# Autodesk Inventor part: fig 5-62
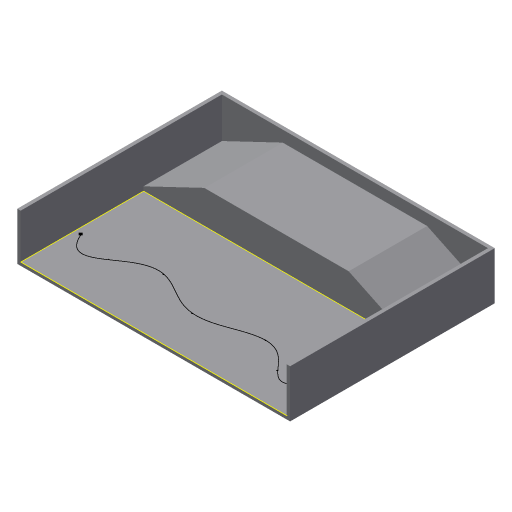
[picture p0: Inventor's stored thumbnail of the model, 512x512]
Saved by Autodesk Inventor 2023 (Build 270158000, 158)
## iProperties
Created: 2004-05
Part Number: fig 5-62
Document SubType Name: Modeling
Designer: CADCIM Technologies
Manufacturer: Standard
Standards Organization: Custom
Density: 1 g/cm^3
Material: Generic
Appearance: Default
Author: CADCIM Technologies
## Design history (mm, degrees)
sketch "Sketch1"
  geometry: L1 (-40, -30)-(40, -30); L2 (40, -30)-(40, 30); L3 (40, 30)-(-40, 30); L4 (-40, 30)-(-40, -30); 1 further point
  constraints: 8 end point, 2 parallel, 1 horizontal, 1 perpendicular, 1 other
  dimensions: "d0" = 80 distance of L1.start L1.end; "d1" = 60 distance of L3.end L1.start; "d2" = 30 distance from line of point (0, 0) L1; "d3" = 40 distance from line of point (0, 0) L4
extrude "Extrusion1" new body sketch "Sketch1" distance "d4" = 14; taper "d5" = 0 deg
shell "Shell1" dims "d6" = 1
workplane "Work Plane1"
sketch "Sketch2"
  geometry: L1 (78, -13)-(78, -11.813); L2 (0, -11.813)-(0, -13); L3 (0, -13)-(78, -13); L4 (0, -11.813)-(17.826, -3.295); L5 (17.826, -3.295)-(60.174, -3.295); L6 (60.174, -3.295)-(78, -11.813); L7 (79, -13.795)-(78, -13.795); L8 (78, 0)-(78, -13) reference; L9 (0, -13)-(0, 0) reference; L10 (78, -13)-(0, -13) reference
  constraints: 14 end point, 3 collinear, 2 equal length, 2 vertical, 1 horizontal alignment, 1 parallel, 1 point on line
extrude "Extrusion2" join sketch "Sketch2" stored distance "d8" = 14; taper "d9" = 0 deg
workplane "Work Plane2"
sketch "Sketch4"
  geometry: L1 (78, 36)-(0, 36) reference; L2 (0, 36)-(0, 0) reference; L3 (78, 0)-(0, 0) reference; L4 (78, 0)-(78, 36) reference; 7 further points
  constraints: 7 other
body "Solid1"
other parameters: "d7" = 23, "d18" = 4
